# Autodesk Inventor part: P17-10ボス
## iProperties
Created: 2008-07
Part Number: P17-10ボス
Document SubType Name: Modeling
Designer: y-shimohigashi
Density: 1 g/cm^3
Stock Number: P17-10ボス
Author: y-shimohigashi
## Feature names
1. 回転1 [Revolution]
